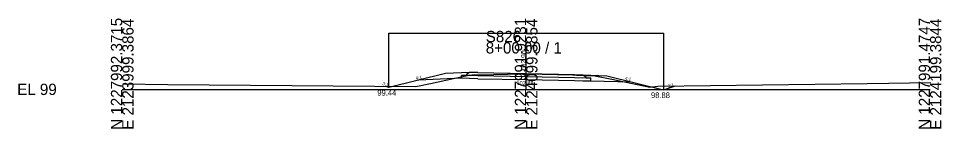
# Model space of a CAD drawing. Extents: x 2118382 to 2118616, y 1213030 to 1222057.
# Drawn here: x 2118381.9 to 2118610.4, y 1218530.1 to 1218557.3 of the extents above; entities that cross this region are included whole.
import ezdxf

# ---------------------------------------------------------------- set-up
doc = ezdxf.new("R2010")
doc.units = 0
for name, color, linetype in [('XS_CELL', 7, 'Continuous'), ('XS_M_DITCH', 7, 'Continuous'), ('XS_P_FINISHED_GRADE', 7, 'Continuous'), ('XS_P_FINISHED_GRADE_ELEV_TX', 7, 'Continuous'), ('XS_P_SUBGRADE_GRANULAR', 7, 'Continuous'), ('XS_P_SUBGRADE_PAVEMENT', 7, 'Continuous'), ('XS_P_TX_DCH', 7, 'Continuous'), ('XS_P_TX_FS_BS', 7, 'Continuous'), ('XS_X_GROUND', 7, 'Continuous'), ('XS_X_GROUND_TX', 7, 'Continuous')]:
    doc.layers.add(name, color=color, linetype=linetype)

msp = doc.modelspace()

# ---------------------------------------------------------------- linework, layer by layer
at = {"layer": 'XS_CELL'}
for p, q in [((2118507.6, 1218539.8), (2118507.6, 1218551.47)), ((2118407.6, 1218539.8), (2118507.6, 1218539.8)), ((2118507.6, 1218539.8), (2118607.6, 1218539.8))]:
    msp.add_line(p, q, dxfattribs=at)
at = {"layer": 'XS_M_DITCH'}
for p, q in [((2118473.6, 1218540.24), (2118473.6, 1218553.7)), ((2118473.6, 1218553.7), (2118541.6, 1218553.7)), ((2118541.6, 1218553.7), (2118541.6, 1218539.68))]:
    msp.add_line(p, q, dxfattribs=at)
at = {"layer": 'XS_P_FINISHED_GRADE'}
for p, q in [((2118487.6, 1218543.74), (2118473.6, 1218540.24)), ((2118493.6, 1218543.98), (2118487.6, 1218543.74)), ((2118495.6, 1218543.94), (2118493.6, 1218543.98)), ((2118495.6, 1218543.94), (2118507.6, 1218543.7)), ((2118507.6, 1218543.7), (2118519.6, 1218543.46)), ((2118519.6, 1218543.46), (2118521.6, 1218543.42)), ((2118521.6, 1218543.42), (2118527.6, 1218543.18)), ((2118527.6, 1218543.18), (2118541.6, 1218539.68)), ((2118473.6, 1218540.24), (2118472.7, 1218540.55)), ((2118541.6, 1218539.68), (2118544.57, 1218540.67))]:
    msp.add_line(p, q, dxfattribs=at)
at = {"layer": 'XS_P_SUBGRADE_GRANULAR'}
for p, q in [((2118492.74, 1218543.25), (2118491.6, 1218543.21)), ((2118491.6, 1218542.53), (2118491.6, 1218543.21)), ((2118491.6, 1218542.53), (2118481.03, 1218542.1)), ((2118493.6, 1218542.48), (2118491.6, 1218542.53)), ((2118495.6, 1218542.44), (2118493.6, 1218542.48)), ((2118495.6, 1218542.44), (2118507.6, 1218542.2)), ((2118507.6, 1218542.2), (2118519.6, 1218541.96)), ((2118519.6, 1218541.96), (2118521.6, 1218541.92)), ((2118521.6, 1218541.92), (2118523.6, 1218541.88)), ((2118522.45, 1218542.65), (2118523.6, 1218542.61)), ((2118523.6, 1218541.88), (2118523.6, 1218542.61)), ((2118523.6, 1218541.88), (2118533.61, 1218541.68))]:
    msp.add_line(p, q, dxfattribs=at)
at = {"layer": 'XS_P_SUBGRADE_PAVEMENT'}
for p, q in [((2118492.91, 1218543.54), (2118492.74, 1218543.25)), ((2118495.6, 1218543.19), (2118492.74, 1218543.25)), ((2118493.6, 1218543.98), (2118492.91, 1218543.54)), ((2118495.6, 1218543.19), (2118507.6, 1218542.95)), ((2118507.6, 1218542.95), (2118519.6, 1218542.71)), ((2118519.6, 1218542.71), (2118522.45, 1218542.65)), ((2118521.6, 1218543.42), (2118522.28, 1218542.95)), ((2118522.28, 1218542.95), (2118522.45, 1218542.65))]:
    msp.add_line(p, q, dxfattribs=at)
at = {"layer": 'XS_X_GROUND'}
for p, q in [((2118483.89, 1218541.28), (2118493.42, 1218543.33)), ((2118493.42, 1218543.33), (2118494.21, 1218543.36)), ((2118494.21, 1218543.36), (2118496.1, 1218543.41)), ((2118496.1, 1218543.41), (2118506.4, 1218543.66)), ((2118506.4, 1218543.66), (2118507.6, 1218543.68)), ((2118507.6, 1218543.68), (2118510.91, 1218543.61)), ((2118510.91, 1218543.61), (2118511.53, 1218543.59)), ((2118511.53, 1218543.59), (2118519.19, 1218543.4)), ((2118519.19, 1218543.4), (2118520.06, 1218543.34)), ((2118520.06, 1218543.34), (2118524.64, 1218543.11)), ((2118524.64, 1218543.11), (2118528.78, 1218542.28)), ((2118407.77, 1218541.13), (2118418.92, 1218541.03)), ((2118418.92, 1218541.03), (2118480.29, 1218540.48)), ((2118480.29, 1218540.48), (2118483.89, 1218541.28)), ((2118528.78, 1218542.28), (2118538.2, 1218540.32)), ((2118538.2, 1218540.32), (2118540.19, 1218540.62)), ((2118540.19, 1218540.62), (2118592.07, 1218541.23)), ((2118592.07, 1218541.23), (2118607.77, 1218541.5))]:
    msp.add_line(p, q, dxfattribs=at)

# ---------------------------------------------------------------- texts
at = {"layer": 'XS_CELL'}
for s, p in [('N 1227992.3715', (2118407.6, 1218529.8)), ('E 2123999.3864', (2118410.4, 1218529.8)), ('N 1227991.9231', (2118507.6, 1218529.8)), ('E 2124099.3854', (2118510.4, 1218529.8)), ('N 1227991.4747', (2118607.6, 1218529.8)), ('E 2124199.3844', (2118610.4, 1218529.8))]:
    msp.add_text(s, height=2.8, rotation=90, dxfattribs=at).set_placement(p)
for s, p in [('S826', (2118497.6, 1218551.47)), ('8+00.00 / 1', (2118497.6, 1218548.67)), ('EL 99', (2118381.6, 1218538.4))]:
    msp.add_text(s, height=2.8, dxfattribs=at).set_placement(p)
at = {"layer": 'XS_P_FINISHED_GRADE_ELEV_TX'}
msp.add_text(' 102.90', height=1.25, rotation=90, dxfattribs=at).set_placement((2118507.6, 1218543.71))
at = {"layer": 'XS_P_TX_DCH'}
for s, p in [('99.44', (2118470.77, 1218538.25)), ('98.88', (2118538.51, 1218537.64))]:
    msp.add_text(s, height=1.4, dxfattribs=at).set_placement(p)
at = {"layer": 'XS_P_TX_FS_BS'}
for s, rotation, p in [('4:1', 14.0362, (2118480.36, 1218542.12)), ('4:1', 345.9638, (2118532.01, 1218542.22)), ('3:1', 341.5651, (2118471.95, 1218540.95)), ('3:1', 18.4349, (2118542.83, 1218540.18))]:
    msp.add_text(s, height=0.8, rotation=rotation, dxfattribs=at).set_placement(p)
at = {"layer": 'XS_X_GROUND_TX'}
msp.add_text('102.88', height=1, dxfattribs=at).set_placement((2118505.2, 1218540.85))

doc.saveas('drawing.dxf')
